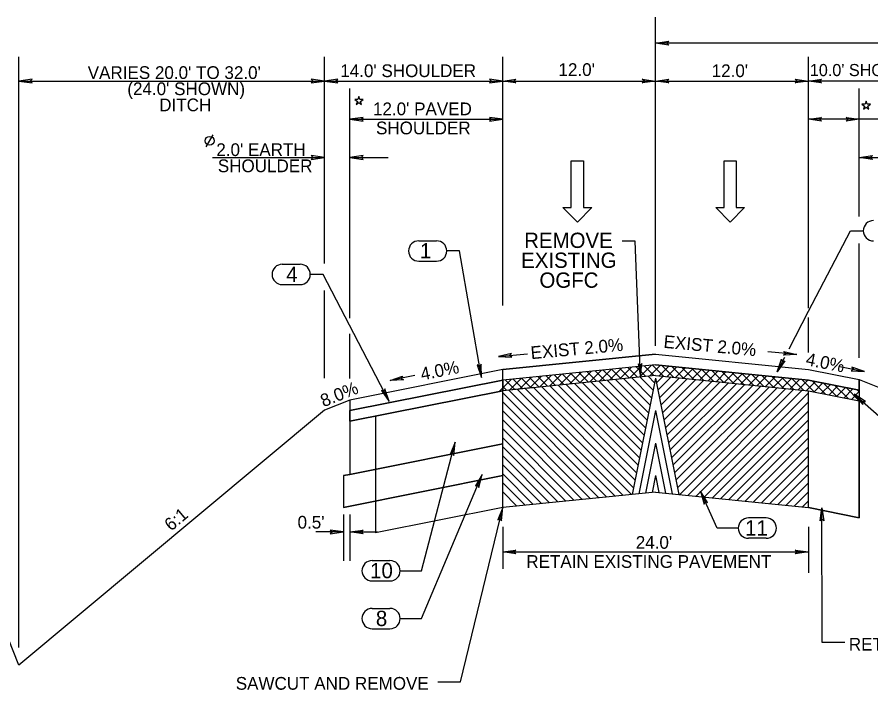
# Model space of a CAD drawing. Extents: x 2003207 to 2014043, y 843846 to 860154.
# Drawn here: x 2013655.7 to 2013722.8, y 844478.2 to 844531 of the extents above; entities that cross this region are included whole.
import ezdxf

# ---------------------------------------------------------------- set-up
doc = ezdxf.new("R2010")
doc.units = 0
for name, color, linetype in [('RD_EX_Road', 7, 'Continuous'), ('RD_QTY_Base_Course', 7, 'Continuous'), ('RD_QTY_ConcPave', 7, 'Continuous'), ('RD_QTY_Intermediate', 7, 'Continuous'), ('RD_QTY_PermVeg', 7, 'Continuous'), ('RD_QTY_Surf_Course', 7, 'Continuous'), ('RD_TX_Misc2', 7, 'Continuous'), ('RD_TX_TypSect', 7, 'Continuous')]:
    doc.layers.add(name, color=color, linetype=linetype)

msp = doc.modelspace()

# ---------------------------------------------------------------- linework, layer by layer
at = {"layer": 'RD_EX_Road'}
for p, q in [((2013705.875, 844502.852), (2013709.031, 844502.536)), ((2013699.505, 844502.215), (2013704.742, 844496.978)), ((2013700.148, 844502.279), (2013704.86, 844497.567)), ((2013700.79, 844502.344), (2013704.978, 844498.156)), ((2013701.433, 844502.408), (2013705.096, 844498.745)), ((2013702.076, 844502.472), (2013705.214, 844499.335)), ((2013702.719, 844502.536), (2013705.332, 844499.924)), ((2013703.362, 844502.601), (2013705.449, 844500.513)), ((2013704.005, 844502.665), (2013705.567, 844501.102)), ((2013705.875, 844502.64), (2013704.047, 844493.503)), ((2013704.647, 844502.729), (2013705.685, 844501.692)), ((2013705.29, 844502.794), (2013705.803, 844502.281)), ((2013705.875, 844502.64), (2013707.702, 844493.503)), ((2013706.46, 844502.794), (2013705.947, 844502.281)), ((2013707.102, 844502.729), (2013706.065, 844501.692)), ((2013707.745, 844502.665), (2013706.183, 844501.102)), ((2013708.388, 844502.601), (2013706.3, 844500.513)), ((2013709.031, 844502.536), (2013706.418, 844499.924)), ((2013709.674, 844502.472), (2013706.536, 844499.335)), ((2013710.317, 844502.408), (2013706.654, 844498.745)), ((2013710.959, 844502.344), (2013706.772, 844498.156)), ((2013711.602, 844502.279), (2013706.89, 844497.567)), ((2013712.245, 844502.215), (2013707.007, 844496.978)), ((2013693.875, 844501.652), (2013683.875, 844499.652)), ((2013696.291, 844501.894), (2013693.875, 844501.652)), ((2013693.875, 844492.485), (2013693.875, 844501.652)), ((2013694.362, 844501.701), (2013702.696, 844493.367)), ((2013695.005, 844501.765), (2013703.338, 844493.432)), ((2013695.648, 844501.829), (2013703.981, 844493.496)), ((2013696.291, 844501.894), (2013704.153, 844494.031)), ((2013696.933, 844501.958), (2013704.271, 844494.62)), ((2013697.576, 844502.022), (2013704.387, 844495.212)), ((2013698.219, 844502.086), (2013704.505, 844495.801)), ((2013698.862, 844502.151), (2013704.623, 844496.39)), ((2013712.888, 844502.151), (2013707.125, 844496.388)), ((2013713.531, 844502.086), (2013707.243, 844495.799)), ((2013714.173, 844502.022), (2013707.361, 844495.21)), ((2013714.816, 844501.958), (2013707.479, 844494.62)), ((2013715.459, 844501.894), (2013707.597, 844494.031)), ((2013716.102, 844501.829), (2013707.769, 844493.496)), ((2013716.745, 844501.765), (2013708.411, 844493.432)), ((2013717.388, 844501.701), (2013709.054, 844493.367)), ((2013717.875, 844492.485), (2013717.875, 844501.652)), ((2013717.875, 844501.652), (2013721.875, 844500.852)), ((2013693.875, 844501.481), (2013702.053, 844493.303)), ((2013717.875, 844501.481), (2013709.697, 844493.303)), ((2013721.875, 844491.685), (2013721.875, 844500.852)), ((2013693.875, 844500.774), (2013701.41, 844493.239)), ((2013717.875, 844500.774), (2013710.34, 844493.239)), ((2013683.875, 844499.652), (2013683.875, 844490.485)), ((2013693.875, 844500.067), (2013700.767, 844493.175)), ((2013705.875, 844500.091), (2013704.568, 844493.555)), ((2013705.875, 844500.091), (2013707.182, 844493.555)), ((2013717.875, 844500.067), (2013710.983, 844493.175)), ((2013693.875, 844499.36), (2013700.124, 844493.11)), ((2013717.875, 844499.36), (2013711.626, 844493.11)), ((2013693.875, 844498.653), (2013699.481, 844493.046)), ((2013717.875, 844498.653), (2013712.268, 844493.046)), ((2013693.875, 844497.945), (2013698.839, 844492.982)), ((2013705.875, 844497.541), (2013705.088, 844493.607)), ((2013705.875, 844497.541), (2013706.662, 844493.607)), ((2013717.875, 844497.945), (2013712.911, 844492.982)), ((2013693.875, 844497.238), (2013698.196, 844492.917)), ((2013717.875, 844497.238), (2013713.554, 844492.917)), ((2013693.875, 844496.531), (2013697.553, 844492.853)), ((2013717.875, 844496.531), (2013714.197, 844492.853)), ((2013693.875, 844495.824), (2013696.91, 844492.789)), ((2013717.875, 844495.824), (2013714.84, 844492.789)), ((2013693.875, 844495.117), (2013696.267, 844492.725)), ((2013705.875, 844494.992), (2013705.608, 844493.659)), ((2013705.875, 844494.992), (2013706.142, 844493.659)), ((2013717.875, 844495.117), (2013715.482, 844492.725)), ((2013693.875, 844494.41), (2013695.624, 844492.66)), ((2013717.875, 844494.41), (2013716.125, 844492.66)), ((2013693.875, 844493.703), (2013694.982, 844492.596)), ((2013705.875, 844493.685), (2013693.875, 844492.485)), ((2013705.875, 844493.685), (2013717.875, 844492.485)), ((2013717.875, 844493.703), (2013716.768, 844492.596)), ((2013717.875, 844492.996), (2013717.411, 844492.532)), ((2013693.875, 844492.485), (2013683.875, 844490.485)), ((2013717.875, 844492.485), (2013721.875, 844491.685))]:
    msp.add_line(p, q, dxfattribs=at)
msp.add_lwpolyline([(2013717.875, 844501.652), (2013721.875, 844500.852), (2013721.875, 844491.685), (2013717.875, 844492.485)], close=True, dxfattribs=at)
at = {"layer": 'RD_QTY_Base_Course'}
for p, q in [((2013693.875, 844497.485), (2013681.875, 844495.085)), ((2013693.875, 844497.485), (2013693.875, 844497.485)), ((2013681.375, 844494.985), (2013681.875, 844495.085)), ((2013681.875, 844495.085), (2013681.375, 844494.985)), ((2013693.875, 844494.985), (2013681.375, 844492.485)), ((2013681.375, 844494.985), (2013681.375, 844492.485)), ((2013681.375, 844494.985), (2013681.375, 844492.485)), ((2013681.375, 844492.485), (2013693.875, 844494.985)), ((2013693.875, 844494.985), (2013693.875, 844494.985))]:
    msp.add_line(p, q, dxfattribs=at)
msp.add_lwpolyline([(2013693.875, 844494.985), (2013693.875, 844497.485)], dxfattribs=at)
at = {"layer": 'RD_QTY_ConcPave'}
for p, q in [((2013721.875, 844502.519), (2013721.875, 844500.852)), ((2013693.875, 844501.652), (2013681.875, 844499.252)), ((2013693.875, 844501.652), (2013693.875, 844501.652)), ((2013681.875, 844499.252), (2013681.875, 844495.085)), ((2013681.875, 844499.252), (2013681.875, 844495.085)), ((2013693.875, 844497.485), (2013681.875, 844495.085)), ((2013681.875, 844495.085), (2013693.875, 844497.485)), ((2013693.875, 844497.485), (2013693.875, 844497.485))]:
    msp.add_line(p, q, dxfattribs=at)
msp.add_lwpolyline([(2013693.875, 844497.485), (2013693.875, 844501.652)], dxfattribs=at)
at = {"layer": 'RD_QTY_Intermediate'}
for p, q in [((2013703.853, 844502.65), (2013704.779, 844503.576)), ((2013704.345, 844503.532), (2013705.102, 844502.775)), ((2013704.639, 844502.728), (2013705.565, 844503.654)), ((2013704.988, 844503.597), (2013705.745, 844502.839)), ((2013705.425, 844502.807), (2013706.264, 844503.646)), ((2013705.631, 844503.661), (2013706.502, 844502.789)), ((2013706.149, 844502.825), (2013706.907, 844503.582)), ((2013706.362, 844503.637), (2013707.288, 844502.711)), ((2013706.792, 844502.76), (2013707.55, 844503.518)), ((2013707.148, 844503.558), (2013708.074, 844502.632)), ((2013705.875, 844502.852), (2013693.875, 844501.652)), ((2013696.782, 844501.943), (2013697.708, 844502.869)), ((2013697.568, 844502.021), (2013698.494, 844502.947)), ((2013697.917, 844502.89), (2013698.674, 844502.132)), ((2013698.354, 844502.1), (2013699.28, 844503.026)), ((2013698.56, 844502.954), (2013699.317, 844502.196)), ((2013699.139, 844502.178), (2013700.065, 844503.104)), ((2013699.202, 844503.018), (2013699.96, 844502.261)), ((2013699.845, 844503.082), (2013700.603, 844502.325)), ((2013699.925, 844502.257), (2013700.851, 844503.183)), ((2013700.488, 844503.147), (2013701.246, 844502.389)), ((2013700.711, 844502.336), (2013701.637, 844503.262)), ((2013701.131, 844503.211), (2013701.888, 844502.453)), ((2013701.496, 844502.414), (2013702.422, 844503.34)), ((2013701.774, 844503.275), (2013702.531, 844502.518)), ((2013702.282, 844502.493), (2013703.208, 844503.419)), ((2013702.416, 844503.34), (2013703.174, 844502.582)), ((2013703.059, 844503.404), (2013703.817, 844502.646)), ((2013703.068, 844502.571), (2013703.994, 844503.497)), ((2013703.702, 844503.468), (2013704.46, 844502.711)), ((2013705.875, 844502.852), (2013717.875, 844501.652)), ((2013707.435, 844502.696), (2013708.193, 844503.454)), ((2013707.933, 844503.48), (2013708.859, 844502.554)), ((2013708.078, 844502.632), (2013708.835, 844503.389)), ((2013708.719, 844503.401), (2013709.645, 844502.475)), ((2013708.721, 844502.567), (2013709.478, 844503.325)), ((2013709.364, 844502.503), (2013710.121, 844503.261)), ((2013709.505, 844503.322), (2013710.431, 844502.396)), ((2013710.006, 844502.439), (2013710.764, 844503.196)), ((2013710.29, 844503.244), (2013711.216, 844502.318)), ((2013710.649, 844502.375), (2013711.407, 844503.132)), ((2013711.076, 844503.165), (2013712.002, 844502.239)), ((2013711.292, 844502.31), (2013712.05, 844503.068)), ((2013711.862, 844503.087), (2013712.788, 844502.161)), ((2013711.935, 844502.246), (2013712.692, 844503.004)), ((2013712.578, 844502.182), (2013713.335, 844502.939)), ((2013712.647, 844503.008), (2013713.573, 844502.082)), ((2013713.22, 844502.117), (2013713.978, 844502.875)), ((2013713.433, 844502.93), (2013714.359, 844502.004)), ((2013714.219, 844502.851), (2013715.145, 844501.925)), ((2013693.875, 844502.485), (2013681.875, 844500.085)), ((2013693.875, 844501.864), (2013694.565, 844502.554)), ((2013693.875, 844502.485), (2013693.875, 844502.485)), ((2013693.875, 844501.652), (2013693.875, 844502.485)), ((2013693.875, 844502.485), (2013693.875, 844502.485)), ((2013694.06, 844502.504), (2013694.817, 844501.746)), ((2013694.425, 844501.707), (2013695.351, 844502.633)), ((2013694.703, 844502.568), (2013695.46, 844501.811)), ((2013695.211, 844501.786), (2013696.137, 844502.712)), ((2013695.345, 844502.632), (2013696.103, 844501.875)), ((2013695.988, 844502.697), (2013696.746, 844501.939)), ((2013695.997, 844501.864), (2013696.922, 844502.79)), ((2013696.631, 844502.761), (2013697.389, 844502.003)), ((2013697.274, 844502.825), (2013698.031, 844502.068)), ((2013713.863, 844502.053), (2013714.621, 844502.811)), ((2013714.506, 844501.989), (2013715.264, 844502.746)), ((2013715.004, 844502.772), (2013715.93, 844501.846)), ((2013715.149, 844501.925), (2013715.906, 844502.682)), ((2013715.79, 844502.694), (2013716.716, 844501.768)), ((2013715.792, 844501.86), (2013716.549, 844502.618)), ((2013716.435, 844501.796), (2013717.192, 844502.554)), ((2013716.576, 844502.615), (2013717.502, 844501.689)), ((2013717.077, 844501.732), (2013717.835, 844502.489)), ((2013717.361, 844502.537), (2013718.339, 844501.559)), ((2013717.72, 844501.668), (2013718.428, 844502.375)), ((2013718.181, 844502.424), (2013719.223, 844501.382)), ((2013718.322, 844501.563), (2013719.017, 844502.257)), ((2013719.065, 844502.247), (2013720.107, 844501.206)), ((2013693.875, 844501.652), (2013681.875, 844499.252)), ((2013681.875, 844499.252), (2013693.875, 844501.652)), ((2013693.622, 844501.627), (2013693.875, 844501.88)), ((2013693.875, 844501.982), (2013694.174, 844501.682)), ((2013717.875, 844501.652), (2013721.875, 844500.852)), ((2013718.912, 844501.445), (2013719.606, 844502.139)), ((2013719.501, 844501.327), (2013720.195, 844502.021)), ((2013719.949, 844502.071), (2013720.991, 844501.029)), ((2013720.09, 844501.209), (2013720.785, 844501.903)), ((2013720.679, 844501.091), (2013721.374, 844501.786)), ((2013720.833, 844501.894), (2013721.874, 844500.852)), ((2013721.269, 844500.973), (2013721.875, 844501.58)), ((2013721.717, 844501.717), (2013721.875, 844501.559)), ((2013721.875, 844501.685), (2013721.875, 844500.852)), ((2013721.858, 844500.855), (2013721.875, 844500.872)), ((2013681.875, 844500.085), (2013681.875, 844499.252)), ((2013681.875, 844500.085), (2013681.875, 844499.252))]:
    msp.add_line(p, q, dxfattribs=at)
msp.add_lwpolyline([(2013681.875, 844500.085), (2013693.875, 844502.485), (2013693.875, 844501.652), (2013681.875, 844499.252)], close=True, dxfattribs=at)
at = {"layer": 'RD_QTY_PermVeg'}
for p, q in [((2013721.875, 844502.519), (2013727.875, 844500.119)), ((2013681.875, 844500.919), (2013679.875, 844500.119)), ((2013679.875, 844500.119), (2013655.875, 844480.119)), ((2013655.875, 844480.119), (2013648.232, 844499.226))]:
    msp.add_line(p, q, dxfattribs=at)
at = {"layer": 'RD_QTY_Surf_Course'}
for p, q in [((2013705.875, 844504.519), (2013693.875, 844503.319)), ((2013705.875, 844504.519), (2013717.875, 844503.319)), ((2013705.875, 844503.685), (2013693.875, 844502.485)), ((2013705.875, 844503.685), (2013717.875, 844502.485)), ((2013693.875, 844503.319), (2013681.875, 844500.919)), ((2013717.875, 844503.319), (2013721.875, 844502.519)), ((2013693.875, 844502.485), (2013681.875, 844500.085)), ((2013717.875, 844502.485), (2013721.875, 844501.685)), ((2013721.875, 844501.685), (2013721.875, 844502.519)), ((2013681.875, 844500.919), (2013681.875, 844500.085))]:
    msp.add_line(p, q, dxfattribs=at)
for points in [[(2013693.875, 844502.485), (2013693.875, 844503.319), (2013705.875, 844504.519), (2013717.875, 844503.319), (2013721.875, 844502.519), (2013721.875, 844501.685), (2013717.875, 844502.485), (2013705.875, 844503.685)], [(2013693.875, 844503.319), (2013681.875, 844500.919), (2013681.875, 844500.085), (2013693.875, 844502.485)]]:
    msp.add_lwpolyline(points, close=True, dxfattribs=at)
at = {"layer": 'RD_TX_Misc2'}
for p, q in [((2013687.282, 844513.417), (2013688.682, 844513.417)), ((2013676.565, 844511.576), (2013677.965, 844511.576)), ((2013687.282, 844511.817), (2013688.682, 844511.817)), ((2013676.565, 844509.976), (2013677.965, 844509.976)), ((2013714.568, 844491.664), (2013713.168, 844491.664)), ((2013714.568, 844490.064), (2013713.168, 844490.064)), ((2013683.622, 844488.318), (2013685.022, 844488.318)), ((2013683.622, 844486.718), (2013685.022, 844486.718)), ((2013683.622, 844484.564), (2013685.022, 844484.564)), ((2013683.622, 844482.964), (2013685.022, 844482.964))]:
    msp.add_line(p, q, dxfattribs=at)
for centre, start, end in [((2013722.991, 844514.207), 90, 270), ((2013687.282, 844512.617), 90, 270), ((2013688.682, 844512.617), 270, 90), ((2013676.565, 844510.776), 90, 270), ((2013677.965, 844510.776), 270, 90), ((2013713.168, 844490.864), 90, 270), ((2013714.568, 844490.864), 270, 90), ((2013683.622, 844487.518), 90, 270), ((2013685.022, 844487.518), 270, 90), ((2013683.622, 844483.764), 90, 270), ((2013685.022, 844483.764), 270, 90)]:
    msp.add_arc(centre, 0.8, start, end, dxfattribs=at)
at = {"layer": 'RD_TX_TypSect'}
for p, q in [((2013705.875, 844505.171), (2013705.875, 844530.976)), ((2013761.875, 844528.924), (2013705.875, 844528.924)), ((2013655.875, 844481.487), (2013655.875, 844527.863)), ((2013679.875, 844511.647), (2013679.875, 844527.863)), ((2013693.875, 844508.328), (2013693.875, 844527.863)), ((2013717.875, 844508.142), (2013717.875, 844527.863)), ((2013655.875, 844525.956), (2013679.875, 844525.956)), ((2013679.875, 844525.956), (2013693.875, 844525.956)), ((2013693.875, 844525.956), (2013705.875, 844525.956)), ((2013705.875, 844525.956), (2013717.875, 844525.956)), ((2013727.875, 844525.956), (2013717.875, 844525.956)), ((2013681.875, 844507.338), (2013681.875, 844525.363)), ((2013721.875, 844515.325), (2013721.875, 844525.363)), ((2013681.875, 844522.956), (2013693.875, 844522.956)), ((2013730.525, 844522.956), (2013717.875, 844522.956)), ((2013670.581, 844520.794), (2013671.147, 844521.737)), ((2013671.088, 844519.956), (2013679.875, 844519.956)), ((2013681.875, 844519.956), (2013684.868, 844519.956)), ((2013721.875, 844519.956), (2013727.875, 844519.956)), ((2013721.875, 844504.233), (2013721.875, 844513.216)), ((2013679.875, 844502.642), (2013679.875, 844509.523)), ((2013717.875, 844504.653), (2013717.875, 844507.387)), ((2013681.875, 844502.599), (2013681.875, 844506.112)), ((2013693.53, 844504.335), (2013695.809, 844504.544)), ((2013716.96, 844504.49), (2013714.681, 844504.698)), ((2013720.334, 844503.54), (2013722.285, 844503.15)), ((2013686.978, 844502.834), (2013685.027, 844502.444)), ((2013681.375, 844491.935), (2013681.375, 844488.295)), ((2013681.875, 844491.935), (2013681.875, 844488.295)), ((2013693.875, 844490.971), (2013693.875, 844487.68)), ((2013717.875, 844490.971), (2013717.875, 844487.366)), ((2013681.375, 844490.564), (2013679.207, 844490.564)), ((2013681.875, 844490.564), (2013684.042, 844490.564)), ((2013693.875, 844488.998), (2013717.875, 844488.998))]:
    msp.add_line(p, q, dxfattribs=at)
for points in [[(2013705.875, 844528.924), (2013706.914, 844529.074), (2013706.754, 844528.924), (2013706.914, 844528.775)], [(2013655.875, 844525.956), (2013656.914, 844525.806), (2013656.754, 844525.956), (2013656.914, 844526.106)], [(2013679.875, 844525.956), (2013678.836, 844526.106), (2013678.996, 844525.956), (2013678.836, 844525.806)], [(2013679.875, 844525.956), (2013680.914, 844525.806), (2013680.754, 844525.956), (2013680.914, 844526.106)], [(2013693.875, 844525.956), (2013692.836, 844526.106), (2013692.996, 844525.956), (2013692.836, 844525.806)], [(2013693.875, 844525.956), (2013694.914, 844526.106), (2013694.754, 844525.956), (2013694.914, 844525.806)], [(2013705.875, 844525.956), (2013704.836, 844525.806), (2013704.996, 844525.956), (2013704.836, 844526.106)], [(2013705.875, 844525.956), (2013706.914, 844526.106), (2013706.754, 844525.956), (2013706.914, 844525.806)], [(2013717.875, 844525.956), (2013716.836, 844525.806), (2013716.996, 844525.956), (2013716.836, 844526.106)], [(2013717.875, 844525.956), (2013718.914, 844526.106), (2013718.754, 844525.956), (2013718.914, 844525.806)], [(2013682.917, 844524.511), (2013682.663, 844524.511), (2013682.584, 844524.753), (2013682.505, 844524.511), (2013682.251, 844524.511), (2013682.457, 844524.361), (2013682.378, 844524.119), (2013682.584, 844524.269), (2013682.79, 844524.119), (2013682.711, 844524.361)], [(2013722.752, 844524.146), (2013722.497, 844524.146), (2013722.419, 844524.388), (2013722.34, 844524.146), (2013722.086, 844524.146), (2013722.292, 844523.997), (2013722.213, 844523.755), (2013722.419, 844523.904), (2013722.625, 844523.755), (2013722.546, 844523.997)], [(2013681.875, 844522.956), (2013682.914, 844522.806), (2013682.754, 844522.956), (2013682.914, 844523.106)], [(2013693.875, 844522.956), (2013692.836, 844523.106), (2013692.996, 844522.956), (2013692.836, 844522.806)], [(2013717.875, 844522.956), (2013718.914, 844523.106), (2013718.754, 844522.956), (2013718.914, 844522.806)], [(2013721.875, 844522.956), (2013720.836, 844522.806), (2013720.996, 844522.956), (2013720.836, 844523.106)], [(2013679.875, 844519.956), (2013678.836, 844520.106), (2013678.996, 844519.956), (2013678.836, 844519.806)], [(2013681.875, 844519.956), (2013682.914, 844519.806), (2013682.754, 844519.956), (2013682.914, 844520.106)], [(2013699.257, 844519.692), (2013700.217, 844519.692), (2013700.217, 844516.023), (2013700.869, 844516.023), (2013699.737, 844514.892), (2013698.606, 844516.023), (2013699.257, 844516.023)], [(2013711.257, 844519.692), (2013712.217, 844519.692), (2013712.217, 844516.023), (2013712.869, 844516.023), (2013711.737, 844514.892), (2013710.606, 844516.023), (2013711.257, 844516.023)], [(2013721.875, 844519.956), (2013722.914, 844520.106), (2013722.754, 844519.956), (2013722.914, 844519.806)], [(2013693.53, 844504.335), (2013694.578, 844504.281), (2013694.405, 844504.415), (2013694.551, 844504.579)], [(2013716.96, 844504.49), (2013715.912, 844504.435), (2013716.084, 844504.57), (2013715.939, 844504.734)], [(2013692.201, 844502.684), (2013692.172, 844503.733), (2013692.052, 844503.55), (2013691.877, 844503.682)], [(2013704.689, 844502.733), (2013704.805, 844503.776), (2013704.66, 844503.612), (2013704.505, 844503.767)], [(2013715.413, 844503.133), (2013715.76, 844504.123), (2013715.819, 844503.912), (2013716.026, 844503.984)], [(2013722.285, 844503.15), (2013721.296, 844503.5), (2013721.424, 844503.322), (2013721.237, 844503.206)], [(2013685.027, 844502.444), (2013686.016, 844502.794), (2013685.888, 844502.616), (2013686.075, 844502.5)], [(2013684.968, 844500.807), (2013684.621, 844501.798), (2013684.562, 844501.586), (2013684.355, 844501.659)], [(2013721.475, 844501.384), (2013722.15, 844500.581), (2013722.131, 844500.799), (2013722.35, 844500.805)], [(2013690.152, 844497.621), (2013689.742, 844496.655), (2013689.928, 844496.771), (2013690.032, 844496.578)], [(2013692.27, 844495.078), (2013691.727, 844494.18), (2013691.928, 844494.269), (2013692.003, 844494.063)], [(2013709.405, 844493.757), (2013709.691, 844492.747), (2013709.763, 844492.954), (2013709.965, 844492.869)], [(2013693.875, 844492.485), (2013693.484, 844491.512), (2013693.667, 844491.632), (2013693.775, 844491.441)], [(2013718.936, 844492.465), (2013719.093, 844491.427), (2013718.942, 844491.586), (2013718.793, 844491.425)], [(2013681.375, 844490.564), (2013680.336, 844490.714), (2013680.496, 844490.564), (2013680.336, 844490.414)], [(2013681.875, 844490.564), (2013682.914, 844490.714), (2013682.754, 844490.564), (2013682.914, 844490.414)], [(2013693.875, 844488.998), (2013694.914, 844489.148), (2013694.754, 844488.998), (2013694.914, 844488.848)], [(2013717.875, 844488.998), (2013716.836, 844488.848), (2013716.996, 844488.998), (2013716.836, 844489.148)]]:
    msp.add_lwpolyline(points, close=True, dxfattribs=at)
for points in [[(2013717.888, 844507.882), (2013721.182, 844514.207), (2013722.191, 844514.207)], [(2013704.689, 844502.733), (2013704.267, 844513.386), (2013703.258, 844513.386)], [(2013692.201, 844502.684), (2013690.491, 844512.617), (2013689.482, 844512.617)], [(2013684.968, 844500.807), (2013679.774, 844510.776), (2013678.765, 844510.776)], [(2013716.356, 844504.943), (2013717.888, 844507.882)], [(2013715.413, 844503.133), (2013716.018, 844504.293)], [(2013721.475, 844501.384), (2013724.951, 844498.31), (2013725.96, 844498.31)], [(2013685.822, 844487.518), (2013687.488, 844487.518), (2013690.152, 844497.621)], [(2013685.822, 844483.764), (2013687.488, 844483.764), (2013692.27, 844495.078)], [(2013712.368, 844490.864), (2013710.703, 844490.864), (2013709.405, 844493.757)], [(2013688.772, 844478.808), (2013690.547, 844478.808), (2013693.875, 844492.485)], [(2013720.745, 844481.876), (2013718.97, 844481.876), (2013718.936, 844492.465)]]:
    msp.add_lwpolyline(points, dxfattribs=at)
msp.add_circle((2013670.864, 844521.266), 0.35, dxfattribs=at)

# ---------------------------------------------------------------- texts
at = {"layer": 'RD_TX_Misc2'}
for s, p in [('REMOVE ', (2013695.557, 844512.855)), ('1', (2013687.371, 844512.033)), ('EXISTING ', (2013695.319, 844511.293)), ('4', (2013676.879, 844510.191)), ('OGFC', (2013696.757, 844509.73)), ('11', (2013712.908, 844490.279)), ('10', (2013683.46, 844486.933)), ('8', (2013683.913, 844483.179))]:
    msp.add_text(s, height=1.2, dxfattribs=at).set_placement(p)
at = {"layer": 'RD_TX_TypSect'}
for s, height, p in [("VARIES 20.0' TO 32.0'", 1, (2013661.285, 844526.119)), ("14.0' SHOULDER", 1, (2013681.119, 844526.266)), ("12.0'", 1, (2013698.252, 844526.355)), ("12.0'", 1, (2013710.283, 844526.264)), ("10.0' SHOULDER", 0.95, (2013717.99, 844526.345)), ("(24.0' SHOWN)", 1, (2013664.395, 844524.851)), ('DITCH', 1, (2013666.899, 844523.584)), ("12.0' PAVED", 1, (2013683.687, 844523.274)), ('SHOULDER', 1, (2013683.923, 844521.774)), ("2.0' EARTH", 1, (2013671.384, 844520.069)), ('SHOULDER', 1, (2013671.502, 844518.802)), ("0.5'", 1, (2013677.764, 844490.827)), ("24.0'", 1, (2013704.321, 844489.245)), ('RETAIN EXISTING PAVEMENT', 1, (2013695.723, 844487.745)), ('RETAIN EXISTING ', 1, (2013721.053, 844481.254)), ('SAWCUT AND REMOVE', 1, (2013672.908, 844478.18))]:
    msp.add_text(s, height=height, dxfattribs=at).set_placement(p)
for s, rotation, p in [('EXIST 2.0%', 5.2184, (2013696.111, 844504.122)), ('EXIST 2.0%', 354.7816, (2013706.475, 844505.02)), ('4.0%', 348.69007, (2013717.619, 844503.667)), ('4.0%', 11.30993, (2013687.527, 844502.453)), ('8.0%', 21.80141, (2013679.804, 844500.349)), ('6:1', 40.23158, (2013667.835, 844490.584))]:
    msp.add_text(s, height=1, rotation=rotation, dxfattribs=at).set_placement(p)

doc.saveas('drawing.dxf')
